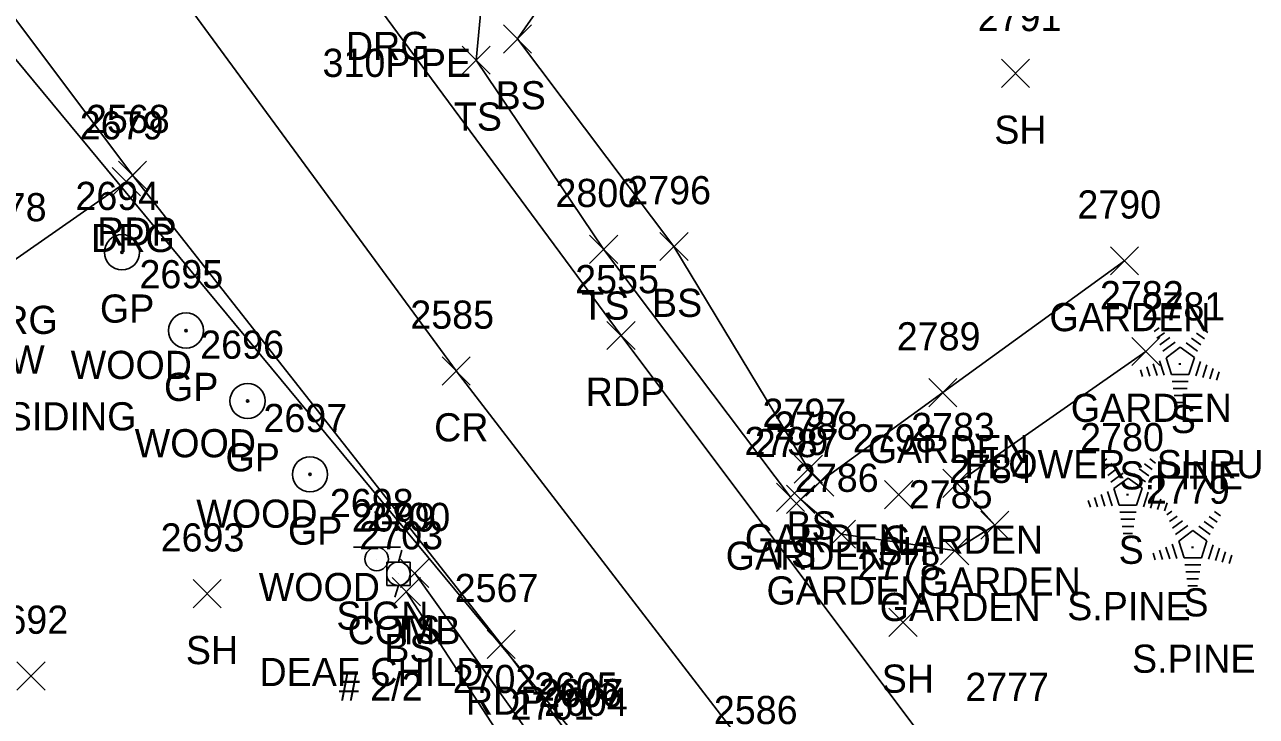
# Model space of a CAD drawing. Extents: x 1634209 to 1639641, y 608564 to 612258.
# Drawn here: x 1639241.2 to 1639328.7, y 611070.4 to 611119.5 of the extents above; entities that cross this region are included whole.
import ezdxf

# ---------------------------------------------------------------- set-up
doc = ezdxf.new("R2010")
doc.units = 0
for name, color, linetype in [('C_C', 7, 'Continuous'), ('D_C', 7, 'Continuous'), ('D_I', 7, 'Continuous'), ('DCP', 7, 'Continuous'), ('L_A', 7, 'Continuous'), ('L_C', 7, 'Continuous'), ('L_I', 7, 'Continuous'), ('L_TIC', 7, 'Continuous'), ('LAPB', 7, 'Continuous'), ('LELB', 7, 'Continuous'), ('LTC', 7, 'Continuous'), ('P_A', 7, 'Continuous'), ('P_I', 7, 'Continuous'), ('P_TIC', 7, 'Continuous'), ('PET', 7, 'Continuous'), ('PRC', 7, 'Continuous'), ('R_A', 7, 'Continuous'), ('R_C', 7, 'Continuous'), ('R_I', 7, 'Continuous'), ('R_TIC', 7, 'Continuous'), ('RDG', 7, 'Continuous'), ('RGP', 7, 'Continuous'), ('S_A', 7, 'Continuous'), ('S_C', 7, 'Continuous'), ('S_I', 7, 'Continuous'), ('SSGN', 7, 'Continuous'), ('U_A', 7, 'Continuous'), ('U_C', 7, 'Continuous'), ('U_I', 7, 'Continuous'), ('UP', 7, 'Continuous')]:
    doc.layers.add(name, color=color, linetype=linetype)

msp = doc.modelspace()

# ---------------------------------------------------------------- linework, layer by layer
at = {"layer": 'DCP'}
msp.add_lwpolyline([(1639280.744, 611068.51), (1639160.798, 611213.264)], dxfattribs=at)
at = {"layer": 'L_TIC'}
for points in [[(1639275.188, 611117.497), (1639277.188, 611119.497)], [(1639277.188, 611117.497), (1639275.188, 611119.497)], [(1639272.254, 611115.984), (1639274.254, 611117.984)], [(1639274.254, 611115.984), (1639272.254, 611117.984)], [(1639310.566, 611115.05), (1639312.566, 611117.05)], [(1639312.566, 611115.05), (1639310.566, 611117.05)], [(1639281.306, 611102.561), (1639283.306, 611104.561)], [(1639283.306, 611102.561), (1639281.306, 611104.561)], [(1639286.298, 611102.758), (1639288.298, 611104.758)], [(1639288.298, 611102.758), (1639286.298, 611104.758)], [(1639318.307, 611101.744), (1639320.307, 611103.744)], [(1639320.307, 611101.744), (1639318.307, 611103.744)], [(1639319.821, 611095.304), (1639321.821, 611097.304)], [(1639321.821, 611095.304), (1639319.821, 611097.304)], [(1639305.396, 611092.38), (1639307.396, 611094.38)], [(1639307.396, 611092.38), (1639305.396, 611094.38)], [(1639295.849, 611086.952), (1639297.849, 611088.952)], [(1639297.849, 611086.952), (1639295.849, 611088.952)], [(1639296.667, 611086.041), (1639298.667, 611088.041)], [(1639298.667, 611086.041), (1639296.667, 611088.041)], [(1639306.408, 611085.944), (1639308.408, 611087.944)], [(1639308.408, 611085.944), (1639306.408, 611087.944)], [(1639294.577, 611084.949), (1639296.577, 611086.949)], [(1639296.577, 611084.949), (1639294.577, 611086.949)], [(1639302.264, 611085.138), (1639304.264, 611087.138)], [(1639304.264, 611085.138), (1639302.264, 611087.138)], [(1639295.306, 611084.8), (1639297.306, 611086.8)], [(1639297.306, 611084.8), (1639295.306, 611086.8)], [(1639298.207, 611082.335), (1639300.207, 611084.335)], [(1639300.207, 611082.335), (1639298.207, 611084.335)], [(1639309.097, 611082.97), (1639311.097, 611084.97)], [(1639311.097, 611082.97), (1639309.097, 611084.97)], [(1639306.241, 611081.162), (1639308.241, 611083.162)], [(1639308.241, 611081.162), (1639306.241, 611083.162)], [(1639267.882, 611079.556), (1639269.882, 611081.556)], [(1639269.882, 611079.556), (1639267.882, 611081.556)], [(1639253.139, 611078.101), (1639255.139, 611080.101)], [(1639255.139, 611078.101), (1639253.139, 611080.101)], [(1639267.283, 611078.253), (1639269.283, 611080.253)], [(1639269.283, 611078.253), (1639267.283, 611080.253)], [(1639302.571, 611076.074), (1639304.571, 611078.074)], [(1639304.571, 611076.074), (1639302.571, 611078.074)], [(1639240.626, 611072.259), (1639242.626, 611074.259)], [(1639242.626, 611072.259), (1639240.626, 611074.259)]]:
    msp.add_lwpolyline(points, dxfattribs=at)
at = {"layer": 'LAPB'}
msp.add_lwpolyline([(1639320.821, 611096.304), (1639307.408, 611086.944), (1639310.097, 611083.97), (1639307.241, 611082.162), (1639299.207, 611083.335), (1639296.306, 611085.8), (1639297.667, 611087.041), (1639306.396, 611093.38), (1639319.307, 611102.744)], dxfattribs=at)
at = {"layer": 'LELB'}
for points in [[(1639295.577, 611085.949), (1639282.306, 611103.561), (1639273.254, 611116.984), (1639274.035, 611125.297), (1639276.97, 611133.286), (1639287.821, 611141.081)], [(1639293.564, 611137.688), (1639282.929, 611128.202), (1639276.188, 611118.497), (1639287.298, 611103.758), (1639296.849, 611087.952)], [(1639268.882, 611080.556), (1639278.458, 611067.154)], [(1639274.914, 611069.051), (1639268.283, 611079.253)]]:
    msp.add_lwpolyline(points, dxfattribs=at)
at = {"layer": 'LTC'}
for p, q in [((1639321.406, 611097.716), (1639321.76, 611097.973)), ((1639321.615, 611097.25), (1639322.145, 611097.634)), ((1639324.433, 611097.608), (1639324.983, 611097.209)), ((1639324.804, 611097.956), (1639325.223, 611097.651)), ((1639321.825, 611096.784), (1639322.529, 611097.296)), ((1639322.035, 611096.319), (1639322.913, 611096.956)), ((1639322.259, 611095.864), (1639323.271, 611096.598)), ((1639323.271, 611096.598), (1639324.268, 611095.873)), ((1639323.691, 611096.911), (1639324.5, 611096.322)), ((1639324.062, 611097.259), (1639324.741, 611096.766)), ((1639321.805, 611095.644), (1639322.135, 611094.625)), ((1639322.259, 611095.864), (1639322.646, 611094.67)), ((1639324.268, 611095.873), (1639323.877, 611094.67)), ((1639324.705, 611095.602), (1639324.368, 611094.563)), ((1639320.438, 611094.995), (1639320.59, 611094.527)), ((1639320.894, 611095.211), (1639321.105, 611094.56)), ((1639321.349, 611095.428), (1639321.62, 611094.593)), ((1639325.15, 611095.352), (1639324.863, 611094.467)), ((1639325.595, 611095.102), (1639325.358, 611094.372)), ((1639326.039, 611094.851), (1639325.852, 611094.277)), ((1639323.877, 611094.67), (1639322.646, 611094.67)), ((1639323.838, 611094.17), (1639322.694, 611094.17)), ((1639323.755, 611093.67), (1639322.766, 611093.67)), ((1639323.671, 611093.17), (1639322.839, 611093.17)), ((1639323.587, 611092.67), (1639322.912, 611092.67)), ((1639317.698, 611088.432), (1639318.052, 611088.689)), ((1639321.096, 611088.672), (1639321.515, 611088.368)), ((1639317.907, 611087.967), (1639318.436, 611088.351)), ((1639318.117, 611087.501), (1639318.821, 611088.012)), ((1639320.354, 611087.976), (1639321.033, 611087.482)), ((1639320.725, 611088.324), (1639321.274, 611087.925)), ((1639318.326, 611087.035), (1639319.205, 611087.673)), ((1639318.551, 611086.58), (1639319.563, 611087.314)), ((1639319.563, 611087.314), (1639320.56, 611086.589)), ((1639319.983, 611087.627), (1639320.792, 611087.039)), ((1639317.641, 611086.144), (1639317.912, 611085.309)), ((1639318.096, 611086.361), (1639318.427, 611085.342)), ((1639318.551, 611086.58), (1639318.938, 611085.387)), ((1639320.56, 611086.589), (1639320.168, 611085.387)), ((1639320.997, 611086.319), (1639320.659, 611085.279)), ((1639321.442, 611086.068), (1639321.154, 611085.184)), ((1639316.73, 611085.711), (1639316.882, 611085.243)), ((1639317.186, 611085.928), (1639317.397, 611085.276)), ((1639320.168, 611085.387), (1639318.938, 611085.387)), ((1639321.886, 611085.818), (1639321.649, 611085.089)), ((1639322.33, 611085.568), (1639322.144, 611084.994)), ((1639320.13, 611084.887), (1639318.986, 611084.887)), ((1639320.046, 611084.387), (1639319.058, 611084.387)), ((1639322.303, 611084.698), (1639322.658, 611084.956)), ((1639322.513, 611084.233), (1639323.042, 611084.617)), ((1639322.723, 611083.767), (1639323.426, 611084.278)), ((1639324.96, 611084.242), (1639325.639, 611083.748)), ((1639325.331, 611084.59), (1639325.88, 611084.191)), ((1639325.702, 611084.938), (1639326.121, 611084.634)), ((1639319.963, 611083.887), (1639319.131, 611083.887)), ((1639319.879, 611083.387), (1639319.204, 611083.387)), ((1639322.932, 611083.301), (1639323.811, 611083.939)), ((1639323.157, 611082.846), (1639324.168, 611083.581)), ((1639324.168, 611083.581), (1639325.166, 611082.856)), ((1639324.588, 611083.893), (1639325.398, 611083.305)), ((1639322.702, 611082.627), (1639323.033, 611081.608)), ((1639323.157, 611082.846), (1639323.544, 611081.653)), ((1639325.166, 611082.856), (1639324.774, 611081.653)), ((1639325.603, 611082.585), (1639325.265, 611081.545)), ((1639321.336, 611081.977), (1639321.488, 611081.509)), ((1639321.791, 611082.194), (1639322.003, 611081.542)), ((1639322.247, 611082.411), (1639322.518, 611081.575)), ((1639324.774, 611081.653), (1639323.544, 611081.653)), ((1639326.048, 611082.334), (1639325.76, 611081.45)), ((1639326.492, 611082.084), (1639326.255, 611081.355)), ((1639326.936, 611081.834), (1639326.75, 611081.26)), ((1639324.736, 611081.153), (1639323.591, 611081.153)), ((1639324.652, 611080.653), (1639323.664, 611080.653)), ((1639324.568, 611080.153), (1639323.737, 611080.153)), ((1639324.485, 611079.653), (1639323.81, 611079.653))]:
    msp.add_line(p, q, dxfattribs=at)
at = {"layer": 'P_TIC'}
for points in [[(1639247.834, 611107.817), (1639249.834, 611109.817)], [(1639249.834, 611107.817), (1639247.834, 611109.817)], [(1639282.543, 611096.441), (1639284.543, 611098.441)], [(1639284.543, 611096.441), (1639282.543, 611098.441)], [(1639270.83, 611093.919), (1639272.83, 611095.919)], [(1639272.83, 611093.919), (1639270.83, 611095.919)], [(1639274.028, 611074.512), (1639276.028, 611076.512)], [(1639276.028, 611074.512), (1639274.028, 611076.512)]]:
    msp.add_lwpolyline(points, dxfattribs=at)
at = {"layer": 'PET'}
for points in [[(1639410.825, 610892.364), (1639390.458, 610919.541), (1639371.801, 610946.358), (1639349.879, 610975.696), (1639327.189, 611005.386), (1639302.754, 611038.38), (1639275.028, 611075.512), (1639248.834, 611108.817), (1639223.626, 611142.441), (1639205.296, 611166.276), (1639182.184, 611194.122), (1639165.678, 611212.038), (1639150.219, 611225.989), (1639136.405, 611234.042), (1639135.28, 611232.533), (1639130.918, 611235.275), (1639127.562, 611237.663), (1639124.139, 611238.638)], [(1639231.623, 611167.792), (1639256.202, 611134.454), (1639283.543, 611097.441), (1639314.632, 611055.995), (1639346.719, 611013.836), (1639378.41, 610971.724), (1639408.009, 610931.002), (1639426.871, 610904.613)]]:
    msp.add_lwpolyline(points, dxfattribs=at)
at = {"layer": 'PRC'}
msp.add_lwpolyline([(1639145.026, 611260.3), (1639159.742, 611243.634), (1639188.697, 611206.44), (1639218.548, 611167.285), (1639245.48, 611130.825), (1639271.83, 611094.919), (1639293.449, 611066.846), (1639319.074, 611033.054), (1639349.486, 610993.068), (1639374.145, 610959.599), (1639396.768, 610928.589), (1639419.083, 610897.866)], dxfattribs=at)
at = {"layer": 'R_TIC'}
for points in [[(1639247.401, 611107.361), (1639249.401, 611109.361)], [(1639249.401, 611107.361), (1639247.401, 611109.361)]]:
    msp.add_lwpolyline(points, dxfattribs=at)
at = {"layer": 'RDG'}
msp.add_lwpolyline([(1639228.352, 611114.064), (1639233.385, 611117.753), (1639236.991, 611112.584), (1639235.335, 611109.46), (1639240.09, 611102.549), (1639248.401, 611108.361)], dxfattribs=at)
at = {"layer": 'RGP'}
for p, q in [((1639248.086, 611103.35), (1639248.086, 611103.35)), ((1639252.637, 611097.79), (1639252.637, 611097.79)), ((1639257.008, 611092.788), (1639257.008, 611092.788)), ((1639261.444, 611087.58), (1639261.444, 611087.58))]:
    msp.add_line(p, q, dxfattribs=at)
for centre, radius in [((1639248.086, 611103.35), 1.25), ((1639248.086, 611103.35), 0.0833), ((1639252.637, 611097.79), 1.25), ((1639252.637, 611097.79), 0.0833), ((1639257.008, 611092.788), 1.25), ((1639257.008, 611092.788), 0.0833), ((1639261.444, 611087.58), 1.25), ((1639261.444, 611087.58), 0.0833)]:
    msp.add_circle(centre, radius, dxfattribs=at)
at = {"layer": 'SSGN'}
for p, q in [((1639264.533, 611082.399), (1639267.867, 611082.399)), ((1639266.18, 611081.566), (1639266.18, 611081.566))]:
    msp.add_line(p, q, dxfattribs=at)
msp.add_circle((1639266.18, 611081.566), 0.833, dxfattribs=at)
at = {"layer": 'UP'}
for p, q in [((1639267.977, 611082.185), (1639267.727, 611081.352)), ((1639266.894, 611079.685), (1639266.894, 611081.352)), ((1639266.894, 611081.352), (1639268.561, 611081.352)), ((1639268.561, 611081.352), (1639268.561, 611079.685)), ((1639267.727, 611080.518), (1639267.727, 611080.518)), ((1639268.561, 611079.685), (1639266.894, 611079.685)), ((1639267.477, 611078.852), (1639267.727, 611079.685))]:
    msp.add_line(p, q, dxfattribs=at)
msp.add_circle((1639267.727, 611080.518), 0.833, dxfattribs=at)

# ---------------------------------------------------------------- texts
at = {"layer": 'C_C'}
msp.add_text('28.55 COR SIDING', height=2, dxfattribs=at).set_placement((1639225.782, 611090.699))
at = {"layer": 'D_C'}
msp.add_text('310PIPE', height=2, dxfattribs=at).set_placement((1639262.333, 611115.797))
at = {"layer": 'D_I'}
for s, p in [('2605', (1639277.359, 611071.51)), ('2606', (1639277.676, 611071.058)), ('2607', (1639277.736, 611071.049)), ('2604', (1639278.073, 611070.431))]:
    msp.add_text(s, height=2, dxfattribs=at).set_placement(p)
at = {"layer": 'L_A'}
for s, p in [('BS', (1639274.629, 611113.497)), ('TS', (1639271.664, 611111.984)), ('SH', (1639310.055, 611111.05)), ('TS', (1639280.715, 611098.561)), ('BS', (1639285.739, 611098.758)), ('GARDEN', (1639313.976, 611097.744)), ('HOW', (1639236.061, 611094.737)), ('GARDEN', (1639315.491, 611091.304)), ('S', (1639322.597, 611090.507)), ('GARDEN', (1639301.065, 611088.38)), ('BS', (1639295.29, 611082.952)), ('GARDEN', (1639292.336, 611082.041)), ('GARDEN', (1639302.077, 611081.944)), ('GARDEN', (1639290.975, 611080.8)), ('TS', (1639293.986, 611080.949)), ('SH', (1639301.752, 611081.138)), ('S', (1639318.888, 611081.224)), ('GARDEN', (1639304.767, 611078.97)), ('GARDEN', (1639293.876, 611078.335)), ('GARDEN', (1639301.911, 611077.162)), ('S', (1639323.494, 611077.49)), ('TS', (1639267.291, 611075.556)), ('SH', (1639252.627, 611074.101)), ('BS', (1639266.724, 611074.253)), ('SH', (1639302.059, 611072.074))]:
    msp.add_text(s, height=2, dxfattribs=at).set_placement(p)
at = {"layer": 'L_C'}
for s, p in [('FLOWER   SHRUB', (1639307.932, 611087.304)), ('S.PINE', (1639318.943, 611086.507)), ('S.PINE', (1639315.235, 611077.224)), ('S.PINE', (1639319.841, 611073.49))]:
    msp.add_text(s, height=2, dxfattribs=at).set_placement(p)
at = {"layer": 'L_I'}
for s, p in [('2791', (1639308.874, 611119.05)), ('2796', (1639283.984, 611106.758)), ('2800', (1639278.881, 611106.561)), ('2790', (1639315.96, 611105.744)), ('2782', (1639317.562, 611099.304)), ('2781', (1639320.518, 611098.507)), ('2789', (1639303.128, 611096.38)), ('2797', (1639293.589, 611090.952)), ('2788', (1639294.407, 611090.041)), ('2783', (1639304.148, 611089.944)), ('2780', (1639316.156, 611089.224)), ('2799', (1639292.309, 611088.949)), ('2787', (1639293.046, 611088.8)), ('2798', (1639300.004, 611089.138)), ('2784', (1639306.838, 611086.97)), ('2786', (1639295.892, 611086.335)), ('2785', (1639303.982, 611085.162)), ('2779', (1639320.841, 611085.49)), ('2700', (1639265.457, 611083.556)), ('2703', (1639264.944, 611082.253)), ('2693', (1639250.832, 611082.101)), ('2778', (1639300.311, 611080.074)), ('2692', (1639238.319, 611076.259)), ('2702', (1639271.575, 611072.051)), ('2777', (1639307.997, 611071.49)), ('2701', (1639275.687, 611070.154))]:
    msp.add_text(s, height=2, dxfattribs=at).set_placement(p)
at = {"layer": 'LTC'}
for p in [(1639323.153, 611095.611), (1639319.445, 611086.328), (1639324.051, 611082.594)]:
    msp.add_text('.', height=1.037, rotation=270, dxfattribs=at).set_placement(p)
at = {"layer": 'P_A'}
for s, p in [('RDP', (1639246.322, 611103.817)), ('RDP', (1639281.031, 611092.441)), ('CR', (1639270.263, 611089.919)), ('RDP', (1639272.517, 611070.512))]:
    msp.add_text(s, height=2, dxfattribs=at).set_placement(p)
at = {"layer": 'P_I'}
for s, p in [('2568', (1639245.527, 611111.817)), ('2555', (1639280.283, 611100.441)), ('2585', (1639268.57, 611097.919)), ('2567', (1639271.721, 611078.512)), ('2586', (1639290.134, 611069.846))]:
    msp.add_text(s, height=2, dxfattribs=at).set_placement(p)
at = {"layer": 'R_A'}
for s, p in [('DRG', (1639263.993, 611117)), ('DRG', (1639245.889, 611103.361)), ('GP', (1639246.52, 611098.35)), ('DRG', (1639237.578, 611097.549)), ('GP', (1639251.07, 611092.79)), ('GP', (1639255.441, 611087.788)), ('GP', (1639259.877, 611082.58))]:
    msp.add_text(s, height=2, dxfattribs=at).set_placement(p)
at = {"layer": 'R_C'}
for p in [(1639244.441, 611094.35), (1639248.991, 611088.79), (1639253.362, 611083.788), (1639257.798, 611078.58)]:
    msp.add_text('WOOD', height=2, dxfattribs=at).set_placement(p)
at = {"layer": 'R_I'}
for s, p in [('2679', (1639245.086, 611111.361)), ('2694', (1639244.779, 611106.35)), ('2678', (1639236.783, 611105.549)), ('2695', (1639249.33, 611100.79)), ('2696', (1639253.646, 611095.788)), ('2697', (1639258.137, 611090.58))]:
    msp.add_text(s, height=2, dxfattribs=at).set_placement(p)
at = {"layer": 'S_A'}
msp.add_text('SIGN', height=2, dxfattribs=at).set_placement((1639263.318, 611076.546))
at = {"layer": 'S_C'}
msp.add_text('DEAF CHILD', height=2, dxfattribs=at).set_placement((1639257.854, 611072.546))
at = {"layer": 'S_I'}
msp.add_text('2698', height=2, dxfattribs=at).set_placement((1639262.853, 611084.546))
at = {"layer": 'U_A'}
msp.add_text('COMB', height=2, dxfattribs=at).set_placement((1639264.113, 611075.518))
at = {"layer": 'U_C'}
msp.add_text('# 2/2', height=2, dxfattribs=at).set_placement((1639263.491, 611071.518))
at = {"layer": 'U_I'}
msp.add_text('2699', height=2, dxfattribs=at).set_placement((1639264.412, 611083.518))

doc.saveas('drawing.dxf')
